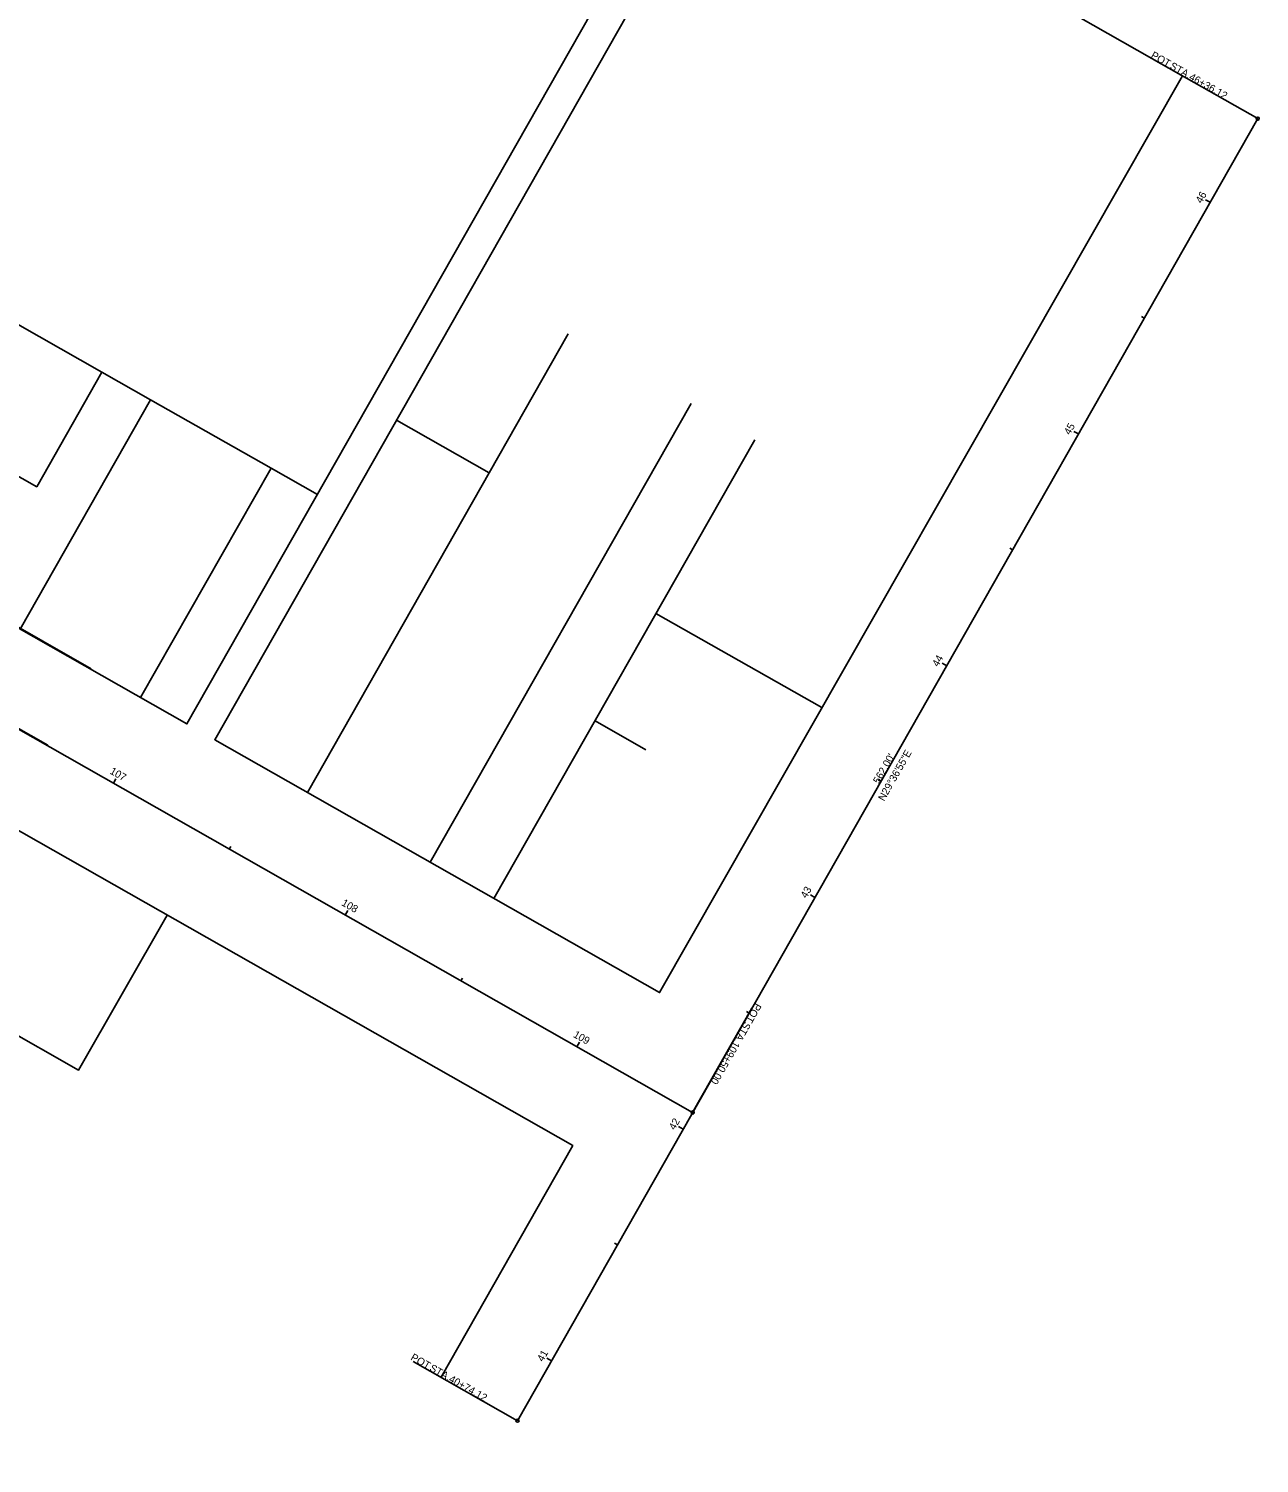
# Model space of a CAD drawing. Extents: x 119320 to 120701, y 385020 to 386199.
# Drawn here: x 120240 to 120701, y 385192 to 385730 of the extents above; entities that cross this region are included whole.
import ezdxf

# ---------------------------------------------------------------- set-up
doc = ezdxf.new("R2010")
doc.units = 0
for name, color, linetype in [('DV_X_Property_Line', 7, 'Continuous'), ('RW_X_CL', 7, 'Continuous'), ('RW_X_CL_100_Bearings', 7, 'Continuous'), ('RW_X_CL_100_Cardinal_Points', 7, 'Continuous'), ('RW_X_CL_100_Distances', 7, 'Continuous'), ('RW_X_CL_100_Stations', 7, 'Continuous'), ('RW_X_Fee_RW', 7, 'Continuous'), ('SC_Scratch1', 7, 'Continuous')]:
    doc.layers.add(name, color=color, linetype=linetype)

msp = doc.modelspace()

# ---------------------------------------------------------------- linework, layer by layer
at = {"layer": 'DV_X_Property_Line'}
for p, q in [((120344.32, 385443.51), (120442.17, 385615.64)), ((120390.4, 385417.32), (120488.24, 385589.45)), ((120377.74, 385583.25), (120412.52, 385563.48)), ((120414.31, 385403.73), (120512.15, 385575.86)), ((120330.65, 385565.16), (120348.04, 385555.27)), ((120537.25, 385475.33), (120475.09, 385510.66)), ((120471.33, 385459.54), (120452.21, 385470.41))]:
    msp.add_line(p, q, dxfattribs=at)
for points in [[(120156.66, 385607.12), (120242.73, 385558.2), (120267.19, 385601.23), (120181.12, 385650.16)], [(120236.52, 385504.79), (120285.44, 385590.85), (120267.19, 385601.23)], [(120281.73, 385479.09), (120330.65, 385565.16), (120285.44, 385590.85)], [(120291.71, 385397.5), (120258.44, 385339.34), (120199.48, 385372.85), (120232.59, 385431.1)]]:
    msp.add_lwpolyline(points, dxfattribs=at)
at = {"layer": 'RW_X_CL'}
for p, q in [((119491.69, 385890.22), (120488.85, 385323.4)), ((120423.12, 385207.77), (120700.85, 385696.36))]:
    msp.add_line(p, q, dxfattribs=at)
at = {"layer": 'RW_X_CL_100_Cardinal_Points'}
for p, q in [((120700.85, 385696.36), (120661.72, 385718.59)), ((120488.85, 385323.4), (120511.08, 385362.52)), ((120423.12, 385207.77), (120384, 385230.01))]:
    msp.add_line(p, q, dxfattribs=at)
for centre in [(120700.85, 385696.36), (120488.85, 385323.4), (120423.12, 385207.77)]:
    msp.add_circle(centre, 0.6, dxfattribs=at)
at = {"layer": 'RW_X_CL_100_Stations'}
for p, q in [((120683, 385664.95), (120681.26, 385665.94)), ((120658.29, 385621.49), (120657.24, 385622.08)), ((120633.58, 385578.02), (120631.84, 385579.01)), ((120608.87, 385534.55), (120607.83, 385535.14)), ((120584.16, 385491.08), (120582.42, 385492.07)), ((120271.5, 385446.94), (120272.49, 385448.68)), ((120559.45, 385447.61), (120558.41, 385448.21)), ((120314.97, 385422.23), (120315.57, 385423.28)), ((120534.74, 385404.15), (120533.01, 385405.13)), ((120358.44, 385397.52), (120359.43, 385399.26)), ((120401.91, 385372.82), (120402.5, 385373.86)), ((120510.04, 385360.68), (120508.99, 385361.27)), ((120445.38, 385348.11), (120446.37, 385349.85)), ((120488.85, 385323.4), (120489.44, 385324.44)), ((120485.33, 385317.21), (120483.59, 385318.2)), ((120460.62, 385273.74), (120459.58, 385274.33)), ((120435.91, 385230.27), (120434.17, 385231.26))]:
    msp.add_line(p, q, dxfattribs=at)
at = {"layer": 'RW_X_Fee_RW'}
msp.add_lwpolyline([(120132.2, 385564.09), (120299.11, 385469.21), (120494.81, 385813.47), (120327.45, 385908.6)], close=True, dxfattribs=at)
for points in [[(120672.59, 385712.42), (120476.46, 385368.4), (120309.55, 385463.28), (120505.24, 385807.54), (120672.16, 385712.66)], [(119920.57, 385191.78), (120099.58, 385506.71), (120443.85, 385311.02), (120394.43, 385224.08)]]:
    msp.add_lwpolyline(points, dxfattribs=at)
at = {"layer": 'SC_Scratch1'}
for p, q in [((120132.89, 385564.16), (120263.23, 385489.92)), ((120087.8, 385551.87), (120246.89, 385461.24))]:
    msp.add_line(p, q, dxfattribs=at)

# ---------------------------------------------------------------- texts
at = {"layer": 'RW_X_CL_100_Bearings'}
msp.add_text('N29°36\'55"E', height=2.8, rotation=60.3847, dxfattribs=at).set_placement((120560.66, 385440.03))
at = {"layer": 'RW_X_CL_100_Cardinal_Points'}
for s, rotation, p in [('POT', 330.3847, (120660.5, 385719.33)), (' STA. ', 330.3847, (120666.7, 385715.81)), ('46+36.12', 330.3847, (120674.81, 385711.2)), ('POT', 240.3847, (120512.4, 385364.76)), (' STA. ', 240.3847, (120508.88, 385358.57)), ('109+50.00', 240.3847, (120504.27, 385350.46)), ('POT', 330.3847, (120382.78, 385230.75)), (' STA. ', 330.3847, (120388.97, 385227.23)), ('40+74.12', 330.3847, (120397.08, 385222.62))]:
    msp.add_text(s, height=2.8, rotation=rotation, dxfattribs=at).set_placement(p)
at = {"layer": 'RW_X_CL_100_Distances'}
msp.add_text("562.00'", height=2.8, rotation=60.3847, dxfattribs=at).set_placement((120558.77, 385446.49))
at = {"layer": 'RW_X_CL_100_Stations'}
for s, rotation, p in [('46', 60.3847, (120679.77, 385664.33)), ('45', 60.3847, (120630.37, 385577.44)), ('44', 60.3847, (120580.92, 385490.44)), ('107', 330.3847, (120269.92, 385450.72)), ('43', 60.3847, (120531.54, 385403.57)), ('108', 330.3847, (120356.85, 385401.3)), ('109', 330.3847, (120443.81, 385351.87)), ('42', 60.3847, (120482.12, 385316.62)), ('41', 60.3847, (120432.7, 385229.68))]:
    msp.add_text(s, height=2.8, rotation=rotation, dxfattribs=at).set_placement(p)

doc.saveas('drawing.dxf')
